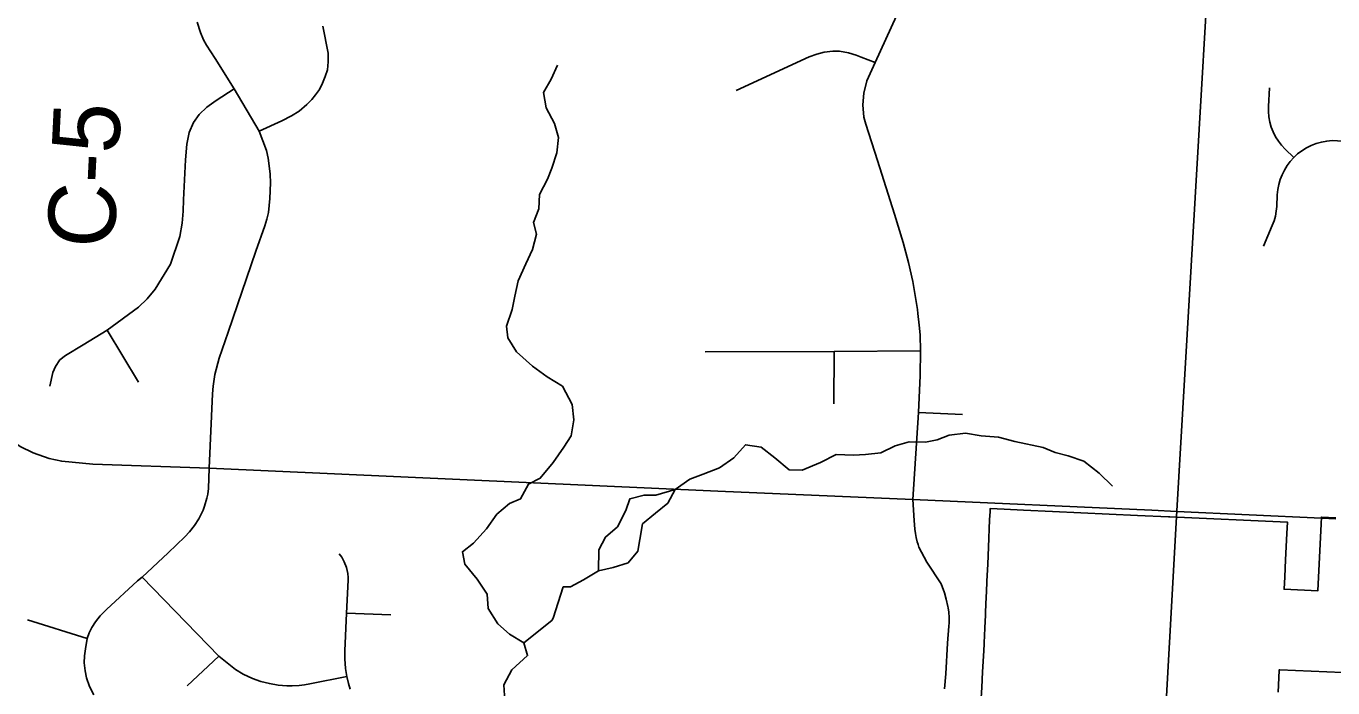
# Model space of a CAD drawing. Extents: x 114843 to 284848, y 317643 to 566895.
# Drawn here: x 168629 to 174457, y 471547 to 474500 of the extents above; entities that cross this region are included whole.
import ezdxf

# ---------------------------------------------------------------- set-up
doc = ezdxf.new("R2010")
doc.units = 0
for name, color, linetype in [('GM_X_Corporation', 7, 'Continuous'), ('GM_X_County_Road', 7, 'Continuous'), ('GM_X_County_Road_Text', 7, 'Continuous'), ('GM_X_Minor_River', 7, 'Continuous'), ('GM_X_Township', 7, 'Continuous'), ('GM_X_Township_Road', 7, 'Continuous')]:
    doc.layers.add(name, color=color, linetype=linetype)

msp = doc.modelspace()

# ---------------------------------------------------------------- linework, layer by layer
at = {"layer": 'GM_X_Corporation'}
for points in [[(172887.3, 471478.5), (172891, 471548.2), (172894.7, 471618.3), (172898.4, 471688.1), (172901.2, 471741.2), (172902, 471758.3), (172902.5, 471770.6), (172905, 471824.4), (172905.4, 471834.7), (172909.5, 471925.2), (172910.5, 471947.2), (172913.6, 472015.6), (172913.9, 472023.7), (172917.3, 472098.9), (172920.7, 472175.1), (172926.2, 472296.9), (172927.8, 472333.8), (172928.4, 472347.1), (172990.2, 472344), (173077.7, 472340), (173207, 472334), (173584.9, 472316.7), (173723.5, 472310.3), (173729.4, 472310.1), (174254.4, 472285.9), (174251.9, 472236.1), (174246, 472119.1), (174242.2, 472043.1), (174239.4, 471986.9), (174389.2, 471979.4), (174404.2, 472279.1), (174406, 472309), (174470.1, 472306.1)], [(174778.4, 471603.2), (174220.9, 471627.6), (174217.9, 471627.7), (174217.7, 471624.3), (174212.6, 471527.2)]]:
    msp.add_lwpolyline(points, dxfattribs=at)
at = {"layer": 'GM_X_County_Road'}
msp.add_line((174406.3, 472304.9), (174470.2, 472301.9), dxfattribs=at)
for points in [[(168015.6, 472609.8), (168203.3, 472640.7), (168285.7, 472660.1), (168392.8, 472691.1), (168426.4, 472696.7), (168500.2, 472699.2), (168546.7, 472664.7), (168603.4, 472624.1), (168660.6, 472595.7), (168731.3, 472570.7), (168787.8, 472558.4), (168926.1, 472545.9), (169445.3, 472527.4), (171714.5, 472424.7), (172583.9, 472387.6), (173649.6, 472339.4)], [(173649.6, 472339.4), (173761.5, 472334.3), (174406.3, 472304.9)]]:
    msp.add_lwpolyline(points, dxfattribs=at)
at = {"layer": 'GM_X_Minor_River'}
for points in [[(170764, 471488.7), (170759.7, 471560.8), (170795.5, 471627), (170865.4, 471691.4), (170849.1, 471747.4), (170784.8, 471787.1), (170732.5, 471833), (170690.1, 471900.9), (170685.8, 471964.9), (170641.4, 472032.8), (170585, 472098.7), (170574.8, 472154.7), (170624.7, 472192.9), (170682.6, 472257.3), (170728.4, 472321.5), (170784.3, 472369.8), (170834.4, 472390.1), (170870.1, 472456.3), (170922.2, 472482.6), (170980, 472552.9), (171027.8, 472621.2), (171059.7, 472671.4), (171071.4, 472743.6), (171065.1, 472811.6), (171020.6, 472893.6), (170952.3, 472935.3), (170887.9, 472983.1), (170815.5, 473046.9), (170777.1, 473108.8), (170770.9, 473160.9), (170796.6, 473235.1), (170808.4, 473295.3), (170824.1, 473363.4), (170857.9, 473439.7), (170887.7, 473503.9), (170905.4, 473572.1), (170891.2, 473624.1), (170915, 473684.3), (170918.7, 473748.4), (170954.5, 473816.7), (170974.3, 473866.9), (170996.1, 473935.1), (171003.8, 474003.2), (170985.5, 474065.3), (170949.1, 474135.2), (170936.8, 474203.3), (170970.6, 474263.6), (170998.4, 474325.8)], [(171523, 472431.9), (171588.6, 472478.4), (171648.4, 472500.8), (171722.1, 472529.4), (171785.7, 472573.8), (171837.2, 472632.2), (171907.3, 472620.7), (171967.6, 472573.1), (172031.9, 472519.5), (172089.9, 472517.9), (172171.6, 472552.5), (172241.2, 472589), (172319.2, 472585.5), (172373.1, 472587.9), (172441, 472596.4), (172504.7, 472626.8), (172566.5, 472645.3), (172640.5, 472643.8), (172692.4, 472654.2), (172746.2, 472674.5), (172818, 472683), (172888.1, 472671.5), (172966.1, 472666.1), (173038.1, 472646.5), (173164.3, 472619.4), (173218.4, 472597.8), (173276.4, 472582.2), (173346.6, 472558.6), (173414.9, 472505.1), (173473.3, 472447.4)], [(171182, 472069.4), (171247.8, 472083.8), (171313.6, 472104.3), (171357.2, 472156.6), (171366.8, 472208.7), (171378.3, 472278.8), (171435.8, 472327.3), (171491.5, 472371.7), (171523, 472431.9)], [(171182, 472069.4), (171183.3, 472163.4), (171212.8, 472219.7), (171266.4, 472266.1), (171303.9, 472338.4), (171321.5, 472390.5), (171385.3, 472407), (171437.2, 472407.3), (171523, 472431.9)], [(171024.1, 471998.4), (171056.6, 471998.5), (171114.3, 472028.9), (171182, 472069.4)], [(170849.1, 471747.4), (170974, 471847.9), (170978.9, 471858.1), (171024.1, 471998.4)]]:
    msp.add_lwpolyline(points, dxfattribs=at)
at = {"layer": 'GM_X_Township'}
for points in [[(169905.4, 461946.5), (169968.1, 464386.5), (169947, 464678.7), (169899, 465343.8), (169749.8, 465987.7), (169587.5, 466795.7), (170734.8, 466733), (170828.3, 466720.5), (173439.3, 466568.9), (173760.3, 472337.1), (173996.9, 476378.2), (174122.9, 478346.3), (174181.7, 479805.8), (174410.2, 484018.4)], [(174410.2, 484018.4), (174181.7, 479805.8), (174122.9, 478346.3), (173996.9, 476378.2), (173760.3, 472337.1), (173439.3, 466568.9), (170828.3, 466720.5), (170734.8, 466733), (169587.5, 466795.7), (169749.8, 465987.7), (169899, 465343.8), (169947, 464678.7), (169968.1, 464386.5), (169905.4, 461946.5)]]:
    msp.add_lwpolyline(points, dxfattribs=at)
at = {"layer": 'GM_X_Township_Road'}
for p, q in [((168990.8, 473143), (169130.5, 472911.9)), ((172231.2, 472813.8), (172232.2, 473047.4)), ((172608.2, 472776.6), (172804.7, 472766.6)), ((168902, 471767), (168636.1, 471851.1)), ((170058.6, 471881.1), (170255.5, 471873.5)), ((169347.2, 471556.8), (169488.2, 471689.2))]:
    msp.add_line(p, q, dxfattribs=at)
for points in [[(172605.8, 473218), (172603.8, 473235.8), (172583, 473360.6), (172564.7, 473445.8), (172541.2, 473534.2), (172501.2, 473661.5), (172426.6, 473899.7), (172374.1, 474061.9), (172365.7, 474094), (172360.8, 474149.3), (172364.6, 474201), (172379.1, 474256), (172414.9, 474337.5), (172559, 474651.3)], [(169445.3, 472527.4), (169460.4, 472859.4), (169463, 472893.1), (169470.9, 472945.9), (169489.6, 473018.1), (169529.7, 473134.8), (169654.2, 473495.9), (169693.1, 473608.5), (169702.5, 473638.6), (169710.4, 473669), (169716, 473730.1), (169718.9, 473801.1), (169716.9, 473839.2), (169713.2, 473876.3), (169708.6, 473910.9), (169700.6, 473944.6), (169668.9, 474032), (169557.7, 474220.6), (169472.4, 474356.2), (169433.4, 474414.9), (169420.2, 474439.5), (169406.3, 474471.5), (169391.6, 474518.1)], [(169668.9, 474032), (169769.2, 474077.1), (169813.2, 474099), (169847, 474119.8), (169880.6, 474149.8), (169904.1, 474172.6), (169920.3, 474193.2), (169937.6, 474217), (169950.7, 474244.8), (169962.8, 474274.6), (169972.9, 474305.5), (169976.7, 474340.4), (169976.4, 474379.5), (169952.2, 474499.1)], [(172414.9, 474337.5), (172353.2, 474361.5), (172330.9, 474370.8), (172296.8, 474381.4), (172256.9, 474388), (172226.1, 474387.8), (172187.9, 474383.2), (172155, 474375.2), (172121.6, 474362.4), (171796, 474212.4)], [(169557.7, 474220.6), (169477.2, 474168.5), (169435.1, 474138.1), (169401.4, 474105.8), (169376.3, 474069.9), (169356.8, 474025.5), (169345.9, 473972.7), (169339.9, 473903), (169331.3, 473725.5), (169329.8, 473674.6), (169325.5, 473621), (169314.6, 473560.6), (169273.5, 473438.3), (169204.2, 473325.5), (169169.7, 473283.3), (169131.1, 473246.2), (168990.8, 473143), (168883, 473077.8), (168804.6, 473030.2), (168780.2, 473011.6), (168760, 472981.8), (168749, 472954.2), (168735.1, 472893.7)], [(174282.1, 473913.1), (174243.7, 473950.9), (174227.8, 473968.2), (174213.6, 473986.8), (174201.2, 474006.7), (174190.7, 474027.7), (174182.2, 474049.6), (174175.8, 474072.1), (174171.5, 474095.2), (174169.5, 474118.6), (174169.6, 474142), (174173.9, 474224.9)], [(174282.1, 473913.1), (174299.7, 473929.4), (174318.7, 473943.9), (174339, 473956.5), (174360.4, 473967.2), (174382.7, 473975.9), (174405.7, 473982.4), (174429.2, 473986.8), (174453.1, 473988.9), (174477, 473988.8), (174751.6, 473974.4), (174890.4, 473967.1), (174917.6, 473966.7), (174944.7, 473968.2), (174971.7, 473971.7), (175062.4, 473986.9), (175090.1, 473990.4), (175118, 473991.9), (175145.9, 473991.3), (175296.4, 473982.5)], [(174147.3, 473518.4), (174186.6, 473610.4), (174194.3, 473630.9), (174200.2, 473652.1), (174204.2, 473673.6), (174206.3, 473695.5), (174209, 473747.4), (174211.3, 473770.4), (174215.6, 473793.2), (174222, 473815.4), (174230.4, 473837), (174240.6, 473857.7), (174252.8, 473877.4), (174266.6, 473895.9), (174282.1, 473913.1)], [(172583.9, 472387.6), (172608.2, 472776.6), (172615.9, 472940.7), (172617.3, 473050.9), (172615.8, 473122.6), (172611.8, 473164.9), (172605.8, 473218)], [(172617.3, 473050.9), (172232.2, 473047.4), (171657.8, 473047)], [(169445.3, 472527.4), (169443.1, 472436.9), (169439.4, 472411.9), (169435.3, 472393.1), (169424.7, 472357.2), (169418.2, 472340), (169399.7, 472301.9), (169380.1, 472271.2), (169357.5, 472242.7), (169336.3, 472220.8), (169262.8, 472149.2), (169146.2, 472041.7), (169125.3, 472024.2), (168987.4, 471897.3)], [(172740.8, 471904.9), (172740.1, 471909.8), (172732.9, 471942.7), (172724.2, 471970.7), (172709.3, 472011.8), (172646.5, 472107.5), (172610.5, 472174.8), (172606.7, 472186.9), (172603.2, 472199.1), (172598.7, 472217.6), (172595, 472236.5), (172592.3, 472255.5), (172590.5, 472274.7), (172589.6, 472294.1), (172583.9, 472387.6)], [(170073.9, 471541.2), (170066.7, 471566.1), (170059.7, 471597.3), (170054, 471634.1), (170051, 471677.3), (170051.2, 471711.9), (170058.6, 471881.1), (170065, 472027.6), (170065.1, 472039.6), (170063.7, 472057.5), (170058, 472083.9), (170048.3, 472109), (170036.5, 472129.9), (170024.6, 472145.5)], [(169146.2, 472041.7), (169488.2, 471689.2), (169562.9, 471628.4), (169596.6, 471608.7), (169639.2, 471588.9), (169676.2, 471575.9), (169714.1, 471566.1), (169752.8, 471559.7), (169791.9, 471556.7), (169815.4, 471556.5), (169846.8, 471558.2), (169870.1, 471560.8), (169894.3, 471564.9), (170059.7, 471597.3)], [(172725.5, 471542.7), (172731.4, 471610.4), (172738.8, 471745.8), (172744.7, 471822.2), (172745.4, 471836.7), (172745.2, 471861.1), (172743.4, 471885.5), (172740.8, 471904.9)], [(168987.4, 471897.3), (168979.6, 471890), (168959.1, 471868.5), (168938.9, 471842.4), (168922.5, 471815.7), (168911.1, 471792.2), (168902, 471767), (168893.6, 471721.4), (168889.5, 471690.4), (168888.8, 471659.2), (168892, 471622.9), (168898.4, 471592.3), (168911.8, 471552.9), (168930.7, 471515.7)]]:
    msp.add_lwpolyline(points, dxfattribs=at)

# ---------------------------------------------------------------- texts
at = {"layer": 'GM_X_County_Road_Text'}
msp.add_text('C-5', height=300, rotation=87.21262, dxfattribs=at).set_placement((169021.8, 473505))

doc.saveas('drawing.dxf')
